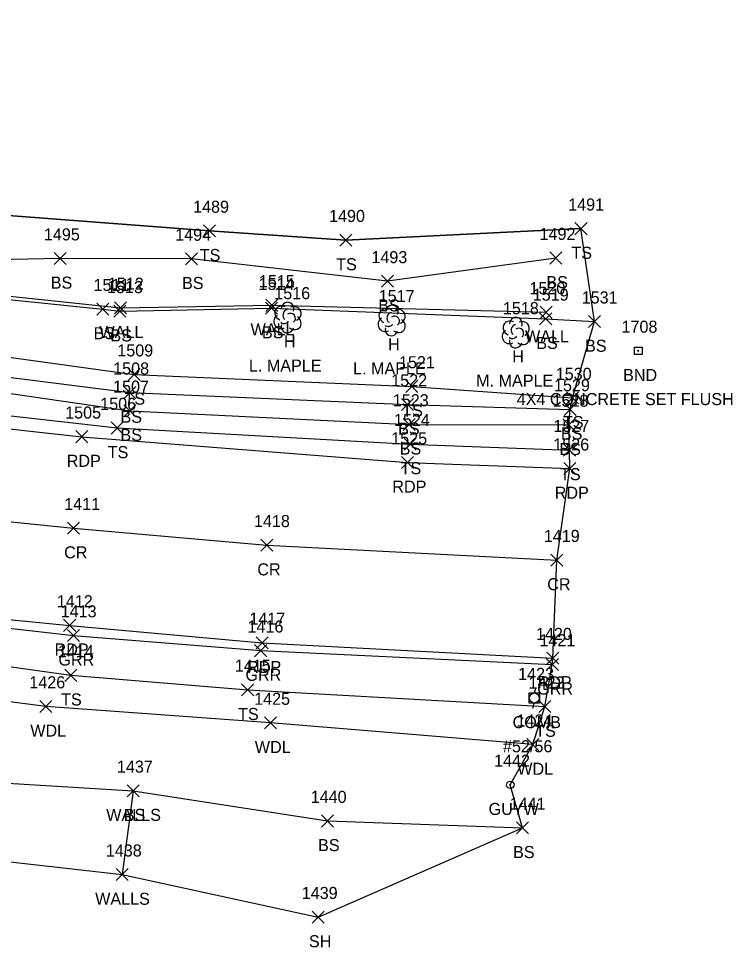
# Model space of a CAD drawing. Extents: x 1547013 to 1549434, y 267998 to 268739.
# Drawn here: x 1548777.6 to 1548895.9, y 268003.9 to 268157.8 of the extents above; entities that cross this region are included whole.
import ezdxf

# ---------------------------------------------------------------- set-up
doc = ezdxf.new("R2010")
doc.units = 0
for name, color, linetype in [('L_A', 7, 'Continuous'), ('L_C', 7, 'Continuous'), ('L_I', 7, 'Continuous'), ('L_TIC', 7, 'Continuous'), ('LAWA', 7, 'Continuous'), ('LELB', 7, 'Continuous'), ('LSOGP', 7, 'Continuous'), ('LTD', 7, 'Continuous'), ('LW', 7, 'Continuous'), ('LWS', 7, 'Continuous'), ('M_A', 7, 'Continuous'), ('M_C', 7, 'Continuous'), ('M_I', 7, 'Continuous'), ('MHBP', 7, 'Continuous'), ('P_A', 7, 'Continuous'), ('P_I', 7, 'Continuous'), ('P_TIC', 7, 'Continuous'), ('PET', 7, 'Continuous'), ('PRC', 7, 'Continuous'), ('R_A', 7, 'Continuous'), ('R_I', 7, 'Continuous'), ('R_TIC', 7, 'Continuous'), ('RGR', 7, 'Continuous'), ('U_A', 7, 'Continuous'), ('U_C', 7, 'Continuous'), ('U_I', 7, 'Continuous'), ('UP', 7, 'Continuous'), ('UPGW', 7, 'Continuous')]:
    doc.layers.add(name, color=color, linetype=linetype)

msp = doc.modelspace()

# ---------------------------------------------------------------- linework, layer by layer
at = {"layer": 'L_TIC'}
for points in [[(1548808.24, 268121.64), (1548810.24, 268123.64)], [(1548810.24, 268121.64), (1548808.24, 268123.64)], [(1548869.82, 268122.01), (1548871.82, 268124.01)], [(1548871.82, 268122.01), (1548869.82, 268124.01)], [(1548830.85, 268120.11), (1548832.85, 268122.11)], [(1548832.85, 268120.11), (1548830.85, 268122.11)], [(1548783.51, 268117.06), (1548785.51, 268119.06)], [(1548785.51, 268117.06), (1548783.51, 268119.06)], [(1548805.27, 268117), (1548807.27, 268119)], [(1548807.27, 268117), (1548805.27, 268119)], [(1548865.65, 268117.14), (1548867.65, 268119.14)], [(1548867.65, 268117.14), (1548865.65, 268119.14)], [(1548837.78, 268113.29), (1548839.78, 268115.29)], [(1548839.78, 268113.29), (1548837.78, 268115.29)], [(1548818.57, 268109.3), (1548820.57, 268111.3)], [(1548820.57, 268109.3), (1548818.57, 268111.3)], [(1548790.6, 268108.68), (1548792.6, 268110.68)], [(1548792.6, 268108.68), (1548790.6, 268110.68)], [(1548793.4, 268108.32), (1548795.4, 268110.32)], [(1548795.4, 268108.32), (1548793.4, 268110.32)], [(1548793.53, 268108.88), (1548795.53, 268110.88)], [(1548795.53, 268108.88), (1548793.53, 268110.88)], [(1548818.52, 268108.84), (1548820.52, 268110.84)], [(1548820.52, 268108.84), (1548818.52, 268110.84)], [(1548864.06, 268108.14), (1548866.06, 268110.14)], [(1548866.06, 268108.14), (1548864.06, 268110.14)], [(1548863.97, 268107.07), (1548865.97, 268109.07)], [(1548865.97, 268107.07), (1548863.97, 268109.07)], [(1548872.06, 268106.6), (1548874.06, 268108.6)], [(1548874.06, 268106.6), (1548872.06, 268108.6)], [(1548795.76, 268097.83), (1548797.76, 268099.83)], [(1548797.76, 268097.83), (1548795.76, 268099.83)], [(1548841.79, 268095.87), (1548843.79, 268097.87)], [(1548843.79, 268095.87), (1548841.79, 268097.87)], [(1548795.07, 268094.83), (1548797.07, 268096.83)], [(1548797.07, 268094.83), (1548795.07, 268096.83)], [(1548868.42, 268093.95), (1548870.42, 268095.95)], [(1548870.42, 268093.95), (1548868.42, 268095.95)], [(1548841.07, 268092.87), (1548843.07, 268094.87)], [(1548843.07, 268092.87), (1548841.07, 268094.87)], [(1548795.06, 268091.83), (1548797.06, 268093.83)], [(1548797.06, 268091.83), (1548795.06, 268093.83)], [(1548868.05, 268092.06), (1548870.05, 268094.06)], [(1548870.05, 268092.06), (1548868.05, 268094.06)], [(1548841.33, 268089.57), (1548843.33, 268091.57)], [(1548843.33, 268089.57), (1548841.33, 268091.57)], [(1548867.8, 268089.49), (1548869.8, 268091.49)], [(1548869.8, 268089.49), (1548867.8, 268091.49)], [(1548792.98, 268088.97), (1548794.98, 268090.97)], [(1548794.98, 268088.97), (1548792.98, 268090.97)], [(1548841.52, 268086.31), (1548843.52, 268088.31)], [(1548843.52, 268086.31), (1548841.52, 268088.31)], [(1548867.94, 268085.32), (1548869.94, 268087.32)], [(1548869.94, 268085.32), (1548867.94, 268087.32)], [(1548785.26, 268047.98), (1548787.26, 268049.98)], [(1548787.26, 268047.98), (1548785.26, 268049.98)], [(1548814.59, 268045.57), (1548816.59, 268047.57)], [(1548816.59, 268045.57), (1548814.59, 268047.57)], [(1548781.15, 268042.82), (1548783.15, 268044.82)], [(1548783.15, 268042.82), (1548781.15, 268044.82)], [(1548863.84, 268042.79), (1548865.84, 268044.79)], [(1548865.84, 268042.79), (1548863.84, 268044.79)], [(1548818.36, 268040.09), (1548820.36, 268042.09)], [(1548820.36, 268040.09), (1548818.36, 268042.09)], [(1548861.84, 268036.49), (1548863.84, 268038.49)], [(1548863.84, 268036.49), (1548861.84, 268038.49)], [(1548795.61, 268028.85), (1548797.61, 268030.85)], [(1548797.61, 268028.85), (1548795.61, 268030.85)], [(1548795.61, 268028.85), (1548797.61, 268030.85)], [(1548797.61, 268028.85), (1548795.61, 268030.85)], [(1548827.81, 268023.84), (1548829.81, 268025.84)], [(1548829.81, 268023.84), (1548827.81, 268025.84)], [(1548860.13, 268022.69), (1548862.13, 268024.69)], [(1548862.13, 268022.69), (1548860.13, 268024.69)], [(1548793.77, 268014.95), (1548795.77, 268016.95)], [(1548795.77, 268014.95), (1548793.77, 268016.95)], [(1548826.25, 268007.91), (1548828.25, 268009.91)], [(1548828.25, 268007.91), (1548826.25, 268009.91)]]:
    msp.add_lwpolyline(points, dxfattribs=at)
at = {"layer": 'LAWA'}
msp.add_lwpolyline([(1548862.84, 268037.49), (1548819.36, 268041.09), (1548782.15, 268043.82), (1548746.65, 268048.37), (1548706.24, 268051.72), (1548673.48, 268054.82), (1548677.13, 268041.37), (1548688.02, 268032.54), (1548723.32, 268029.82)], dxfattribs=at)
at = {"layer": 'LELB'}
for points in [[(1548708.97, 268139.76), (1548694.03, 268130.11), (1548685.4, 268117.11), (1548686.8, 268106.68), (1548701.04, 268101.78), (1548747.94, 268095.17), (1548793.98, 268089.97), (1548842.52, 268087.31), (1548868.94, 268086.32)], [(1548710.97, 268137.11), (1548706.53, 268135.04), (1548704.07, 268132.06), (1548696.31, 268128.63), (1548688.78, 268116.89), (1548689.4, 268111.45), (1548689.24, 268109.65), (1548701.64, 268107.07), (1548747.47, 268099.87), (1548796.06, 268092.83), (1548842.33, 268090.57), (1548868.8, 268090.49)], [(1548706.53, 268135.04), (1548706.78, 268123.66), (1548717.02, 268120.73), (1548732.85, 268126.56), (1548752.22, 268125.19), (1548770.11, 268125.63), (1548809.24, 268122.64), (1548831.85, 268121.11), (1548870.82, 268123.01)], [(1548709.8, 268114.29), (1548739.34, 268118.08), (1548754.48, 268113.46), (1548791.6, 268109.68), (1548794.4, 268109.32), (1548819.52, 268109.84), (1548864.97, 268108.07), (1548873.06, 268107.6)], [(1548866.65, 268118.14), (1548838.78, 268114.29), (1548806.27, 268118), (1548784.51, 268118.06), (1548757.71, 268117.53)], [(1548699.4, 268110.37), (1548747.53, 268101.96), (1548796.07, 268095.83), (1548842.07, 268093.87), (1548869.05, 268093.06)], [(1548752.46, 268104.98), (1548796.76, 268098.83), (1548842.79, 268096.87), (1548869.42, 268094.95)], [(1548662.66, 268068.17), (1548718.89, 268059.45), (1548749.16, 268054.19), (1548786.26, 268048.98), (1548815.59, 268046.57), (1548864.84, 268043.79)], [(1548680.21, 268049.95), (1548724.2, 268041.69), (1548768.54, 268031.54), (1548796.61, 268029.85), (1548828.81, 268024.84), (1548861.13, 268023.69)]]:
    msp.add_lwpolyline(points, dxfattribs=at)
at = {"layer": 'LSOGP'}
msp.add_lwpolyline([(1548760.56, 268019.85), (1548794.77, 268015.95), (1548827.25, 268008.91), (1548861.13, 268023.69), (1548859.11, 268030.83), (1548862.84, 268037.49), (1548864.84, 268043.79), (1548866.07, 268050.79), (1548866.14, 268051.84), (1548866.8, 268068.08), (1548868.98, 268083.24), (1548868.94, 268086.32), (1548868.8, 268090.49), (1548869.05, 268093.06), (1548869.42, 268094.95), (1548873.06, 268107.6), (1548870.82, 268123.01), (1548831.85, 268121.11), (1548809.24, 268122.64), (1548770.11, 268125.63)], dxfattribs=at)
at = {"layer": 'LTD'}
for p, q in [((1548822.17, 268108.32), (1548822.17, 268108.32)), ((1548822.17, 268108.32), (1548822.17, 268108.32)), ((1548839.43, 268107.84), (1548839.43, 268107.84)), ((1548839.43, 268107.84), (1548839.43, 268107.84)), ((1548860, 268105.83), (1548860, 268105.83)), ((1548860, 268105.83), (1548860, 268105.83))]:
    msp.add_line(p, q, dxfattribs=at)
for centre in [(1548822.21, 268109.75), (1548839.47, 268109.27), (1548860.05, 268107.27)]:
    msp.add_arc(centre, 1.05, 335.5272, 180.9563, dxfattribs=at)
for centre, major_axis, ratio, start_param, end_param in [((1548821.37, 268108.99), (1.21, -0.51), 0.895232, 1.570796, 4.712389), ((1548821.96, 268108.78), (-0.208, -0.792), 0.645439, 3.141593, 6.283185), ((1548823.21, 268108.9), (-1.14, -0.48), 0.949671, 1.570796, 4.712389), ((1548838.63, 268108.51), (1.21, -0.51), 0.895232, 1.570796, 4.712389), ((1548840.47, 268108.42), (-1.14, -0.48), 0.949671, 1.570796, 4.712389), ((1548821.08, 268107.61), (0.58, -1.04), 0.959034, 3.141593, 6.283185), ((1548822.67, 268108.15), (-0.5, 0.667), 0.989748, 3.141593, 6.283185), ((1548823.17, 268107.49), (-1.09, 0.79), 0.841452, 1.570796, 4.712389), ((1548838.34, 268107.13), (0.58, -1.04), 0.959034, 3.141593, 6.283185), ((1548839.22, 268108.3), (-0.208, -0.792), 0.645439, 3.141593, 6.283185), ((1548839.93, 268107.67), (-0.5, 0.667), 0.989748, 3.141593, 6.283185), ((1548822.17, 268106.82), (0.26, 1.06), 0.942809, 1.570796, 4.712389), ((1548821.71, 268107.57), (-0.625, -0.083), 0.423636, 0, 3.141593), ((1548839.43, 268106.34), (0.26, 1.06), 0.942809, 1.570796, 4.712389), ((1548838.97, 268107.09), (-0.625, -0.083), 0.423636, 0, 3.141593), ((1548840.43, 268107.01), (-1.09, 0.79), 0.841452, 1.570796, 4.712389), ((1548859.21, 268106.5), (1.21, -0.51), 0.895232, 1.570796, 4.712389), ((1548859.79, 268106.29), (-0.208, -0.792), 0.645439, 3.141593, 6.283185), ((1548860.5, 268105.67), (-0.5, 0.667), 0.989748, 3.141593, 6.283185), ((1548861.04, 268106.42), (-1.14, -0.48), 0.949671, 1.570796, 4.712389), ((1548858.92, 268105.12), (0.58, -1.04), 0.959034, 3.141593, 6.283185), ((1548859.54, 268105.08), (-0.625, -0.083), 0.423636, 0, 3.141593), ((1548861, 268105), (-1.09, 0.79), 0.841452, 1.570796, 4.712389), ((1548860, 268104.33), (0.26, 1.06), 0.942809, 1.570796, 4.712389)]:
    msp.add_ellipse(centre, major_axis=major_axis, ratio=ratio, start_param=start_param, end_param=end_param, dxfattribs=at)
at = {"layer": 'LW'}
msp.add_lwpolyline([(1548755.74, 268113.95), (1548794.53, 268109.88), (1548819.57, 268110.3), (1548865.06, 268109.14)], dxfattribs=at)
at = {"layer": 'LWS'}
msp.add_lwpolyline([(1548796.61, 268029.85), (1548794.77, 268015.95)], dxfattribs=at)
at = {"layer": 'MHBP'}
msp.add_lwpolyline([(1548879.69, 268103.39), (1548880.94, 268103.39), (1548880.94, 268102.14), (1548879.69, 268102.14)], close=True, dxfattribs=at)
msp.add_circle((1548880.31, 268102.76), 0.0833, dxfattribs=at)
at = {"layer": 'P_TIC'}
for points in [[(1548787.11, 268087.53), (1548789.11, 268089.53)], [(1548789.11, 268087.53), (1548787.11, 268089.53)], [(1548841.08, 268083.26), (1548843.08, 268085.26)], [(1548843.08, 268083.26), (1548841.08, 268085.26)], [(1548867.98, 268082.24), (1548869.98, 268084.24)], [(1548869.98, 268082.24), (1548867.98, 268084.24)], [(1548785.74, 268072.36), (1548787.74, 268074.36)], [(1548787.74, 268072.36), (1548785.74, 268074.36)], [(1548817.76, 268069.54), (1548819.76, 268071.54)], [(1548819.76, 268069.54), (1548817.76, 268071.54)], [(1548865.8, 268067.08), (1548867.8, 268069.08)], [(1548867.8, 268067.08), (1548865.8, 268069.08)], [(1548785.09, 268056.26), (1548787.09, 268058.26)], [(1548787.09, 268056.26), (1548785.09, 268058.26)], [(1548817, 268053.36), (1548819, 268055.36)], [(1548819, 268053.36), (1548817, 268055.36)], [(1548865.14, 268050.84), (1548867.14, 268052.84)], [(1548867.14, 268050.84), (1548865.14, 268052.84)]]:
    msp.add_lwpolyline(points, dxfattribs=at)
at = {"layer": 'PET'}
for points in [[(1548291.29, 268251.79), (1548331.75, 268232.06), (1548365.57, 268215.99), (1548397.04, 268199.92), (1548430.53, 268185.01), (1548469.56, 268167.88), (1548505.57, 268153.53), (1548548.45, 268139.73), (1548572.84, 268130.65), (1548596.65, 268123.57), (1548616.57, 268118.19), (1548655.34, 268109.04), (1548680.93, 268103.12), (1548700.8, 268099.76), (1548753.55, 268092.31), (1548788.11, 268088.53), (1548842.08, 268084.26), (1548868.98, 268083.24)], [(1548277.31, 268222.58), (1548324.08, 268200.05), (1548370.89, 268177.56), (1548421.34, 268155.12), (1548457.66, 268139.55), (1548491.25, 268126.1), (1548528.96, 268112.02), (1548568.2, 268099.41), (1548604.28, 268089.49), (1548621.9, 268083.87), (1548638.12, 268079.83), (1548660.94, 268075.04), (1548683.04, 268070.81), (1548718.59, 268065.27), (1548750.02, 268060.75), (1548786.09, 268057.26), (1548818, 268054.36), (1548866.14, 268051.84)]]:
    msp.add_lwpolyline(points, dxfattribs=at)
at = {"layer": 'PRC'}
msp.add_lwpolyline([(1548285.23, 268237.15), (1548330.43, 268214.75), (1548376.37, 268192.58), (1548426.54, 268169.59), (1548464.29, 268153.5), (1548497.35, 268140.09), (1548534.69, 268126.49), (1548572.93, 268114.69), (1548608.02, 268104.77), (1548637.81, 268097.38), (1548663.07, 268091.69), (1548686.38, 268086.96), (1548723.69, 268081.05), (1548751.9, 268076.9), (1548786.74, 268073.36), (1548818.76, 268070.54), (1548866.8, 268068.08)], dxfattribs=at)
at = {"layer": 'R_TIC'}
for points in [[(1548785.73, 268054.59), (1548787.73, 268056.59)], [(1548787.73, 268054.59), (1548785.73, 268056.59)], [(1548816.74, 268052.07), (1548818.74, 268054.07)], [(1548818.74, 268052.07), (1548816.74, 268054.07)], [(1548865.07, 268049.79), (1548867.07, 268051.79)], [(1548867.07, 268049.79), (1548865.07, 268051.79)]]:
    msp.add_lwpolyline(points, dxfattribs=at)
at = {"layer": 'RGR'}
msp.add_lwpolyline([(1548671.73, 268069.35), (1548718.76, 268063.54), (1548749.75, 268059.78), (1548786.73, 268055.59), (1548817.74, 268053.07), (1548866.07, 268050.79)], dxfattribs=at)
at = {"layer": 'UP'}
for p, q in [((1548863.34, 268046.89), (1548863.09, 268046.06)), ((1548862.26, 268044.39), (1548862.26, 268046.06)), ((1548862.26, 268046.06), (1548863.93, 268046.06)), ((1548863.09, 268045.22), (1548863.09, 268045.22)), ((1548863.93, 268046.06), (1548863.93, 268044.39)), ((1548863.93, 268044.39), (1548862.26, 268044.39)), ((1548862.84, 268043.56), (1548863.09, 268044.39))]:
    msp.add_line(p, q, dxfattribs=at)
msp.add_circle((1548863.09, 268045.22), 0.833, dxfattribs=at)
at = {"layer": 'UPGW'}
for radius in [0.625, 0.0833]:
    msp.add_circle((1548859.11, 268030.83), radius, dxfattribs=at)

# ---------------------------------------------------------------- texts
at = {"layer": 'L_A'}
for s, p in [('TS', (1548807.65, 268117.64)), ('TS', (1548869.23, 268118.01)), ('TS', (1548830.25, 268116.11)), ('BS', (1548782.95, 268113.06)), ('BS', (1548804.71, 268113)), ('BS', (1548865.09, 268113.14)), ('BS', (1548837.22, 268109.29)), ('BS', (1548790.04, 268104.68)), ('WALL', (1548791.02, 268104.88)), ('WALL', (1548816.06, 268105.3)), ('BS', (1548817.96, 268104.84)), ('BS', (1548792.84, 268104.32)), ('H', (1548821.6, 268103.32)), ('WALL', (1548861.55, 268104.14)), ('BS', (1548863.41, 268103.07)), ('H', (1548838.86, 268102.84)), ('BS', (1548871.5, 268102.6)), ('H', (1548859.43, 268100.83)), ('TS', (1548795.17, 268093.83)), ('BS', (1548794.51, 268090.83)), ('TS', (1548841.2, 268091.87)), ('TS', (1548867.83, 268089.95)), ('BS', (1548794.5, 268087.83)), ('BS', (1548840.52, 268088.87)), ('BS', (1548867.49, 268088.06)), ('TS', (1548792.39, 268084.97)), ('BS', (1548840.78, 268085.57)), ('BS', (1548867.24, 268085.49)), ('TS', (1548840.93, 268082.31)), ('TS', (1548867.35, 268081.32)), ('TS', (1548784.67, 268043.98)), ('TS', (1548814, 268041.57)), ('WDL', (1548779.56, 268038.82)), ('TS', (1548863.24, 268038.79)), ('WDL', (1548816.77, 268036.09)), ('WDL', (1548860.26, 268032.49)), ('WALLS', (1548792.15, 268024.85)), ('BS', (1548795.05, 268024.85)), ('BS', (1548827.25, 268019.84)), ('BS', (1548859.57, 268018.69)), ('WALLS', (1548790.31, 268010.95)), ('SH', (1548825.74, 268003.91))]:
    msp.add_text(s, height=2, dxfattribs=at).set_placement(p)
at = {"layer": 'L_C'}
for s, p in [('L. MAPLE', (1548815.79, 268099.32)), ('L. MAPLE', (1548833.05, 268098.84)), ('M. MAPLE', (1548853.45, 268096.83))]:
    msp.add_text(s, height=2, dxfattribs=at).set_placement(p)
at = {"layer": 'L_I'}
for s, p in [('1489', (1548806.54, 268125.64)), ('1491', (1548868.7, 268126.01)), ('1490', (1548829.07, 268124.11)), ('1495', (1548781.82, 268121.06)), ('1494', (1548803.58, 268121)), ('1492', (1548863.96, 268121.14)), ('1493', (1548836.09, 268117.29)), ('1511', (1548790.04, 268112.68)), ('1513', (1548792.27, 268112.32)), ('1512', (1548792.41, 268112.88)), ('1514', (1548817.39, 268112.84)), ('1515', (1548817.45, 268113.3)), ('1516', (1548819.99, 268111.32)), ('1517', (1548837.3, 268110.84)), ('1520', (1548862.28, 268112.14)), ('1519', (1548862.83, 268111.07)), ('1531', (1548870.94, 268110.6)), ('1518', (1548857.88, 268108.83)), ('1509', (1548793.98, 268101.83)), ('1508', (1548793.3, 268098.83)), ('1521', (1548840.66, 268099.87)), ('1522', (1548839.38, 268096.87)), ('1530', (1548866.64, 268097.95)), ('1507', (1548793.28, 268095.83)), ('1529', (1548866.35, 268096.06)), ('1506', (1548791.15, 268092.97)), ('1523', (1548839.64, 268093.57)), ('1528', (1548866.11, 268093.49)), ('1524', (1548839.83, 268090.31)), ('1527', (1548866.25, 268089.32)), ('1414', (1548784.14, 268051.98)), ('1415', (1548813.46, 268049.57)), ('1426', (1548779.4, 268046.82)), ('1422', (1548862.14, 268046.79)), ('1425', (1548816.66, 268044.09)), ('1424', (1548860.15, 268040.49)), ('1437', (1548793.92, 268032.85)), ('1437', (1548793.92, 268032.85)), ('1440', (1548826.03, 268027.84)), ('1441', (1548859, 268026.69)), ('1438', (1548792.08, 268018.95)), ('1439', (1548824.55, 268011.91))]:
    msp.add_text(s, height=2, dxfattribs=at).set_placement(p)
at = {"layer": 'M_A'}
msp.add_text('BND', height=2, dxfattribs=at).set_placement((1548877.8, 268097.76))
at = {"layer": 'M_C'}
msp.add_text('4X4 CONCRETE SET FLUSH', height=2, dxfattribs=at).set_placement((1548860.17, 268093.76))
at = {"layer": 'M_I'}
msp.add_text('1708', height=2, dxfattribs=at).set_placement((1548877.54, 268105.76))
at = {"layer": 'P_A'}
for s, p in [('RDP', (1548785.6, 268083.53)), ('RDP', (1548839.56, 268079.26)), ('RDP', (1548866.47, 268078.24)), ('CR', (1548785.17, 268068.36)), ('CR', (1548817.19, 268065.54)), ('CR', (1548865.23, 268063.08)), ('RDP', (1548783.58, 268052.26)), ('RDP', (1548815.49, 268049.36)), ('RDP', (1548863.63, 268046.84))]:
    msp.add_text(s, height=2, dxfattribs=at).set_placement(p)
at = {"layer": 'P_I'}
for s, p in [('1505', (1548785.34, 268091.53)), ('1525', (1548839.38, 268087.26)), ('1526', (1548866.23, 268086.24)), ('1411', (1548785.18, 268076.36)), ('1418', (1548816.63, 268073.54)), ('1419', (1548864.66, 268071.08)), ('1412', (1548783.96, 268060.26)), ('1417', (1548815.87, 268057.36)), ('1420', (1548863.36, 268054.84))]:
    msp.add_text(s, height=2, dxfattribs=at).set_placement(p)
at = {"layer": 'R_A'}
for p in [(1548784.22, 268050.59), (1548815.22, 268048.07), (1548863.56, 268045.79)]:
    msp.add_text('GRR', height=2, dxfattribs=at).set_placement(p)
at = {"layer": 'R_I'}
for s, p in [('1413', (1548784.6, 268058.59)), ('1416', (1548815.56, 268056.07)), ('1421', (1548863.94, 268053.79))]:
    msp.add_text(s, height=2, dxfattribs=at).set_placement(p)
at = {"layer": 'U_A'}
for s, p in [('COMB', (1548859.48, 268040.22)), ('GUYW', (1548855.51, 268025.83))]:
    msp.add_text(s, height=2, dxfattribs=at).set_placement(p)
at = {"layer": 'U_C'}
msp.add_text('#52/56', height=2, dxfattribs=at).set_placement((1548857.9, 268036.22))
at = {"layer": 'U_I'}
for s, p in [('1423', (1548860.4, 268048.22)), ('1442', (1548856.42, 268033.83))]:
    msp.add_text(s, height=2, dxfattribs=at).set_placement(p)

doc.saveas('drawing.dxf')
